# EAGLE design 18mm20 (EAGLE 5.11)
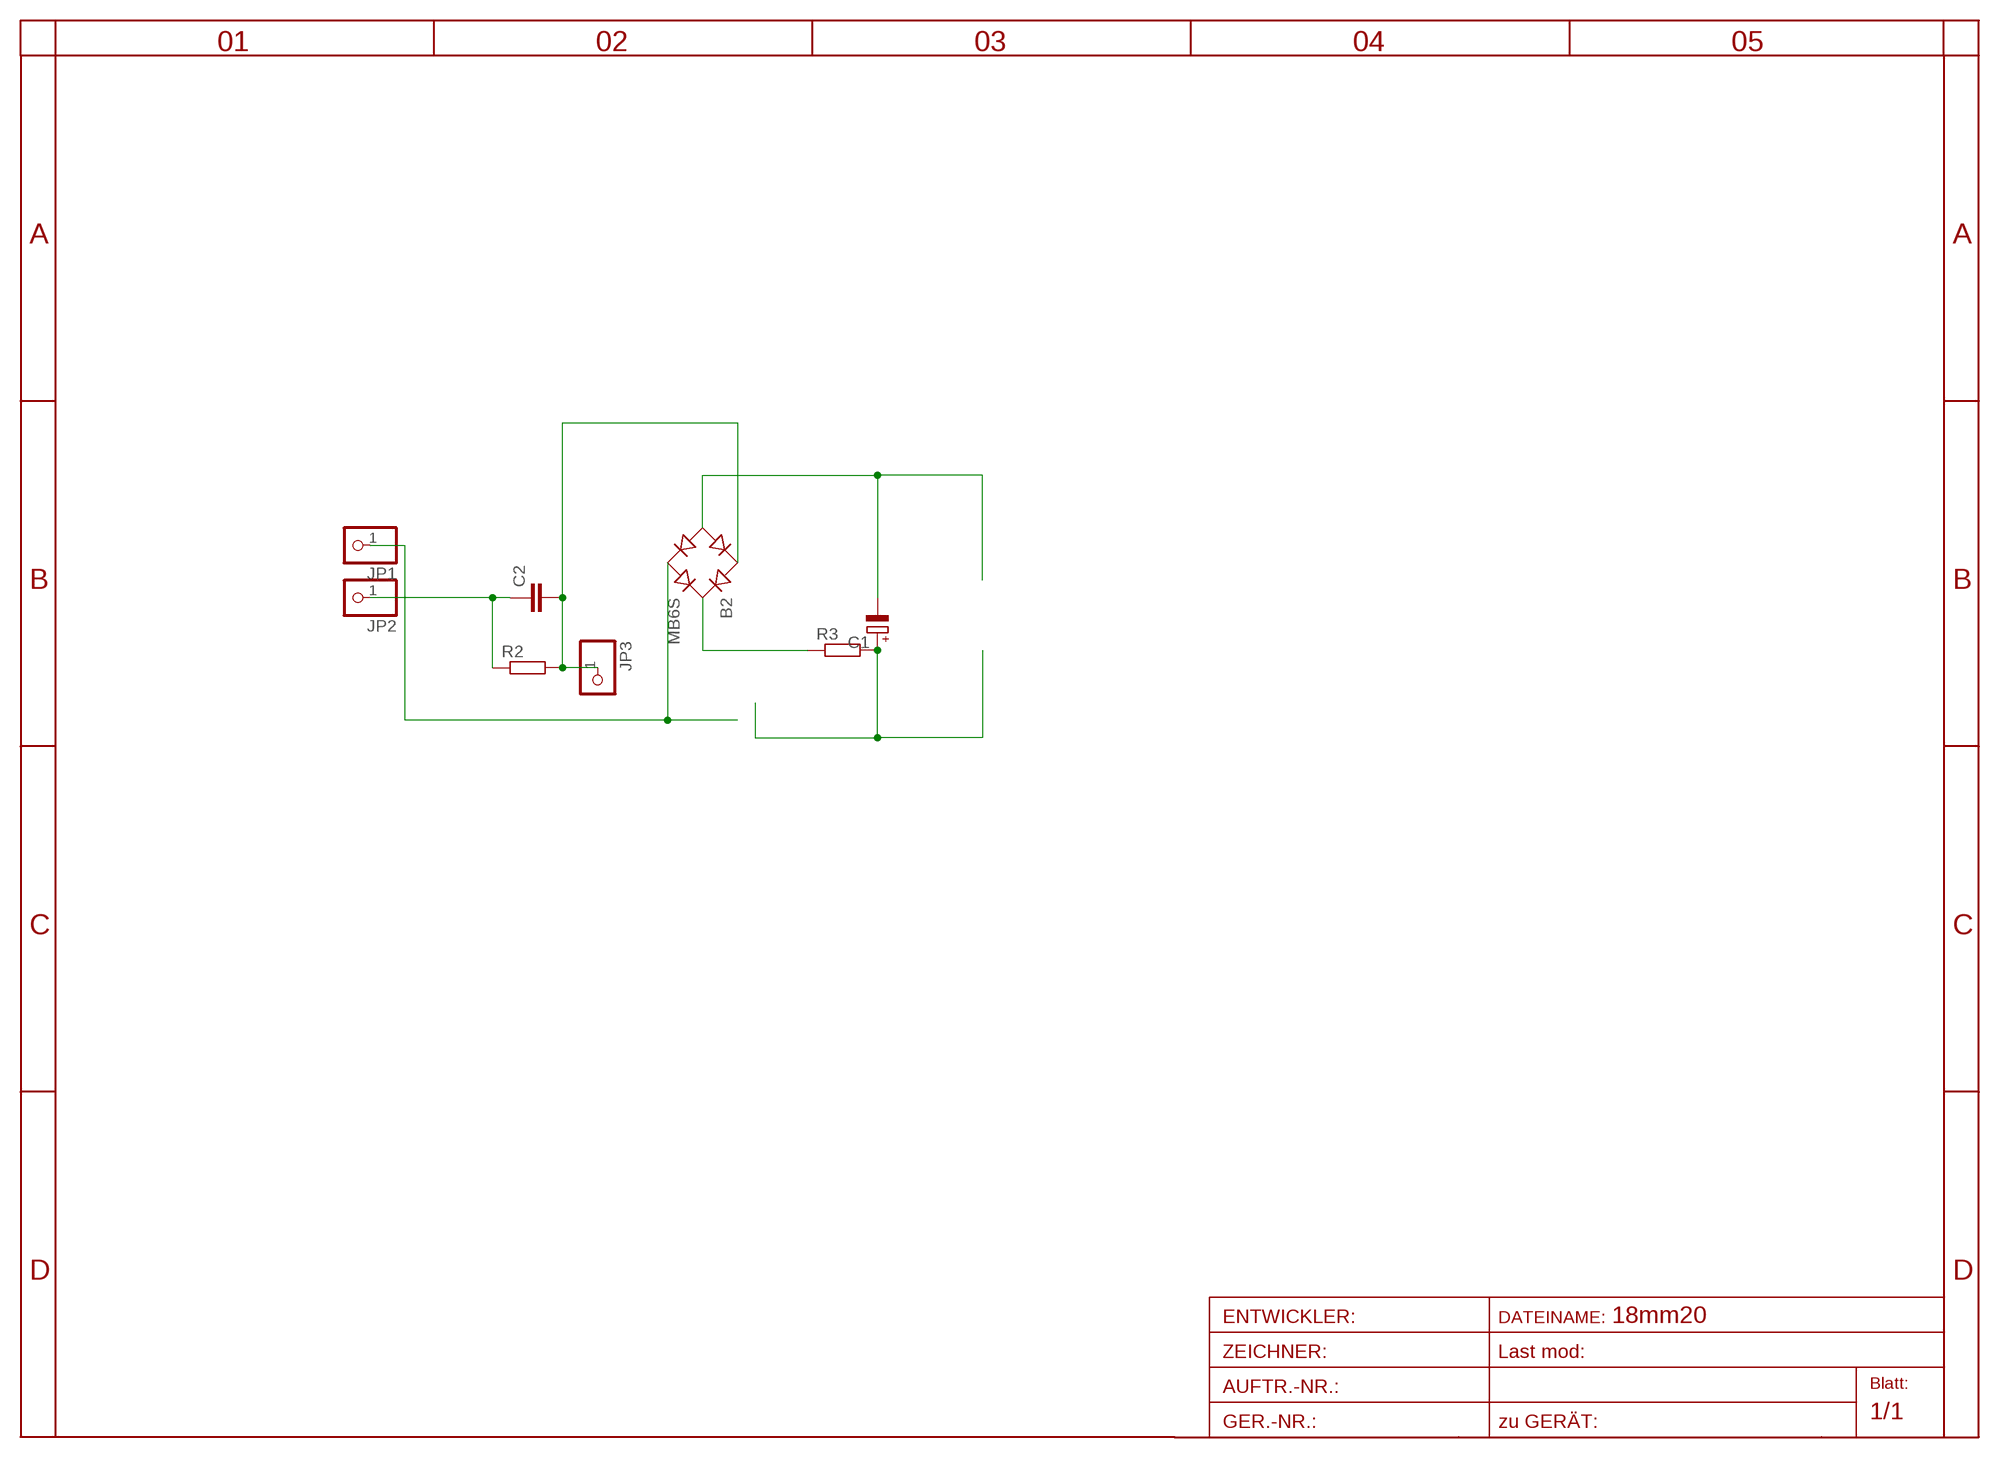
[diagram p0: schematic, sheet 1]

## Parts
B2  MB6S  [SOIC-4]
C1  CPOL-EUE5-13  [E5-13]
C2  C-EUC200  [C200-62]
JP1  PINHD-1X1  [1X01]
JP2  PINHD-1X1  [1X01]
JP3  PINHD-1X1  [1X01]
R2  R-EU_R1206  [R1206]
R3  R-EU_0613/5V  [P0613V]

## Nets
AC1: B2.~1(AC1) C2.2 JP3.1 R2.2
AC2: B2.~2(AC2) JP1.1
AC+: C2.1 JP2.1 R2.1
N$2: B2.+ R3.1
PLUS: C1.+ R3.2
V-: B2.- C1.-

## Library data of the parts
B2 = rectifier:MB*S: Bridge Rectifier Source: http://www.fairchildsemi.com/ds/MB/MB6S.pdf
C1 = rcl-2:CPOL-EU: POLARIZED CAPACITOR, European symbol
C2 = rcl:C-EU: CAPACITOR, European symbol
JP1-JP3 = pinhead:PINHD-1X1: PIN HEADER
R2 R3 = rcl:R-EU_: RESISTOR, European symbol

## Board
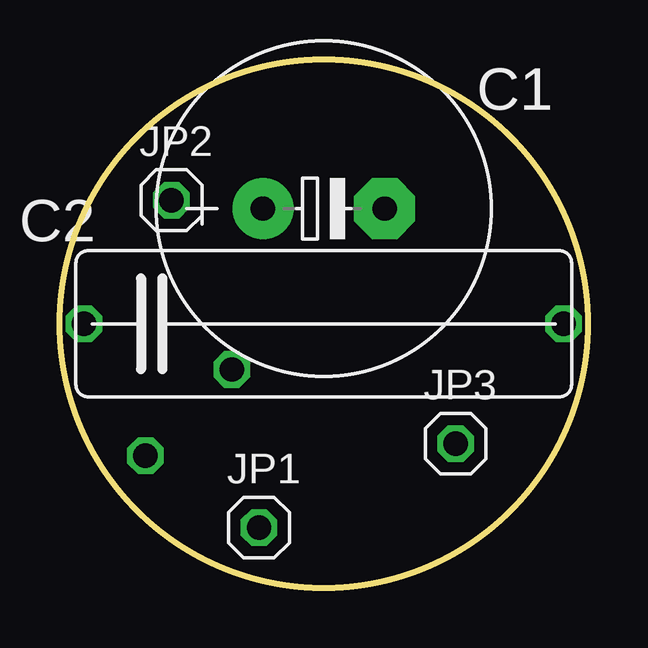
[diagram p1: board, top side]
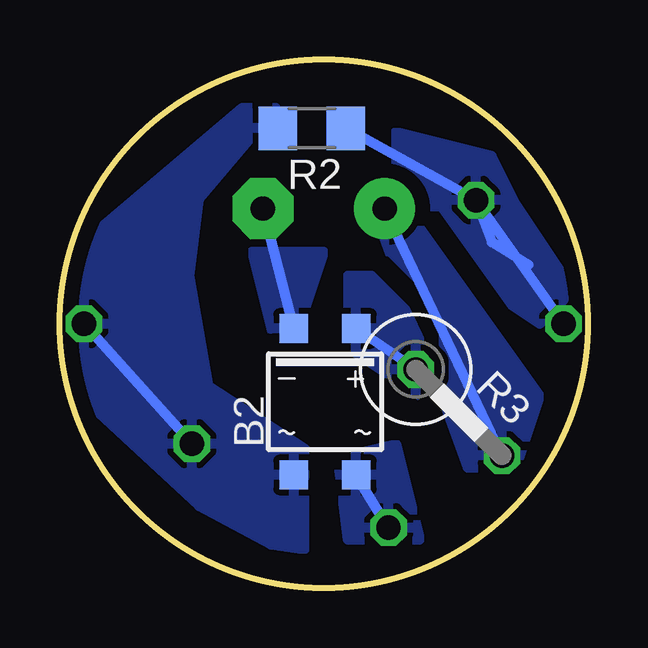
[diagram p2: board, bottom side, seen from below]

Size 22 x 22 mm. Coordinates in mm from the lower left corner, seen from the top.
Outline: circle at 11,11 radius 11
Copper layers (1*16): Top 0.035mm / dielectric 1.5mm / Bottom 0.035mm
Design rules "default *": minimum track width 10mil, minimum drill 24mil, track to track 8mil, track to pad 8mil, pad to pad 8mil, via to via 8mil, smd to smd 8mil, copper to edge 4mil, drill to drill 8mil, minimum pad ring 10mil, minimum via ring 8mil, stop-mask expansion 4mil, vias tented up to drill 0mil, thermal gap 10mil

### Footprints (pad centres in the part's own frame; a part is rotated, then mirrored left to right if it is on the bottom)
SOIC-4 = smd 1.2 x 1.2: + 1.3,3.05; - -1.3,3.05; ~1 -1.3,-3.05; ~2 1.3,-3.05
E5-13 = drill 1.016 pad 2.54 round: + -2.54,0 | drill 1.016 pad 2.54 octagon: - 2.54,0
C200-62 = drill 1.016 octagon: 1 -10,0; 2 10,0
1X01 = drill 1.016 octagon: 1 0,0
R1206 = smd 1.6 x 1.803: 1 -1.422,0; 2 1.422,0
P0613V = drill 1.016 octagon: 1 -2.54,0; 2 2.54,0

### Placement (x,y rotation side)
B2  10.95,7.75 0 bottom
C1  11,15.8 0 top
C2  11,11 0 top
JP1  8.3,2.5 0 top
JP2  4.65,16.15 0 top
JP3  16.5,6 0 top
R2  11.5,19.15 180 bottom
R3  5.36,7.3 315 bottom

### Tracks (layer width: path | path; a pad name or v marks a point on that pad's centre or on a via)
AC1
  Bottom 0.406: JP3.1 C2.2
  pour Bottom (isolate 0.61): 13,20 14.4,20 21,14.4 21.8,8.6 16.2,3.4 13.2,1.8 11.8,1.6 11.8,5.8 15.8,8.4 16.6,13 16.2,16.2
AC2
  Bottom 0.406: JP1.1 B2.~2
  pour Bottom (isolate 0.61): 10.4,5.4 8,6 7,2 10,2
AC+
  Bottom 0.406: 2.46,13.46 4,14.4 JP2.1 | JP2.1 R2.1 | C2.1 JP2.1
  pour Bottom (isolate 0.61, rank 4): 8,19 8,15 2,11 1,12 1,13 3,16 4,18
N$2
  Bottom 0.406: B2.+ 7,9 R3.1
  pour Bottom (isolate 0.61): 9,13 10,13 10,10 7,8 7,11
PLUS
  Bottom 0.406: R3.2 C1.+
  pour Bottom (isolate 0.61, rank 3): 9,16 7,15 2,8 3,5 5,5
V-
  Bottom 0.406: B2.- C1.-
  pour Bottom (isolate 0.61, rank 2): 12,11 11,14 14,14 13,10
